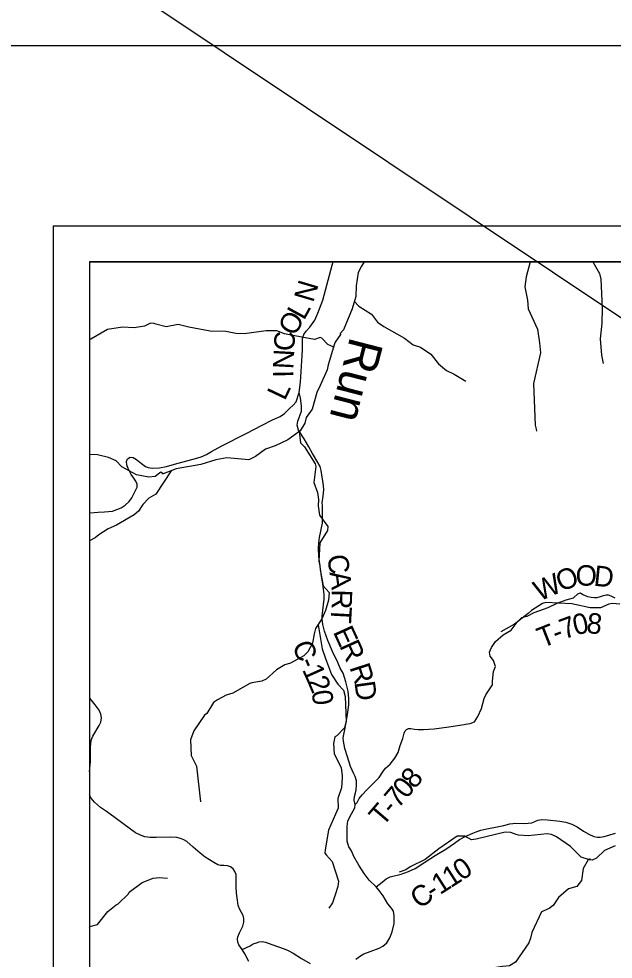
# Model space of a CAD drawing. Extents: x -1.8 to 75.7, y -2 to 25.
# Drawn here: x 1.905 to 3.552, y 18.965 to 21.574 of the extents above; entities that cross this region are included whole.
import ezdxf

# ---------------------------------------------------------------- set-up
doc = ezdxf.new("R2010")
doc.units = 0
for name, color, linetype in [('GM_X_County_Road', 7, 'Continuous'), ('GM_X_County_Road_Text', 7, 'Continuous'), ('GM_X_Minor_River', 7, 'Continuous'), ('GM_X_Minor_River_Text', 7, 'Continuous'), ('GM_X_Township', 7, 'Continuous'), ('GM_X_Township_Road', 7, 'Continuous'), ('GM_X_Township_Road_Text', 7, 'Continuous'), ('GM_X_Township_ROW', 7, 'Continuous'), ('SH_Border', 7, 'Continuous'), ('SH_Data', 7, 'Continuous'), ('TX_P_1', 7, 'Continuous')]:
    doc.layers.add(name, color=color, linetype=linetype)

msp = doc.modelspace()

# ---------------------------------------------------------------- linework, layer by layer
at = {"layer": 'GM_X_County_Road'}
for points in [[(2.6813, 20.5373), (2.685, 20.5663), (2.6879, 20.6104), (2.6901, 20.6398), (2.6908, 20.6552), (2.6903, 20.6757), (2.6911, 20.6875), (2.6944, 20.6986), (2.7004, 20.7075), (2.7107, 20.7182), (2.7245, 20.7376), (2.7332, 20.7569), (2.7469, 20.7938), (2.7732, 20.8906), (2.7756, 20.9)], [(2.4389, 20.3739), (2.4668, 20.3897), (2.5343, 20.4234), (2.5785, 20.447), (2.6077, 20.4615), (2.6288, 20.4708), (2.6406, 20.4791), (2.6548, 20.4931), (2.6644, 20.5022), (2.6733, 20.5116), (2.6813, 20.5373)], [(2.895, 19.1663), (2.8757, 19.184), (2.8613, 19.2025), (2.8465, 19.2258), (2.8334, 19.2502), (2.8262, 19.2657), (2.8195, 19.2767), (2.8147, 19.293), (2.8141, 19.3072), (2.8144, 19.3332), (2.8166, 19.3482), (2.8219, 19.3605), (2.8358, 19.3854), (2.8366, 19.394), (2.834, 19.4063), (2.8345, 19.4167), (2.8393, 19.4339), (2.8407, 19.4489), (2.8401, 19.4596), (2.8364, 19.4718), (2.8316, 19.4813), (2.8279, 19.4898), (2.8238, 19.4998), (2.8155, 19.5263), (2.808, 19.5498), (2.8041, 19.5704), (2.8034, 19.5793), (2.8088, 19.6069), (2.8155, 19.6438), (2.8192, 19.6704), (2.819, 19.6888), (2.8171, 19.7084), (2.8109, 19.7346), (2.8032, 19.759), (2.7954, 19.7727), (2.7884, 19.7882), (2.7742, 19.8187), (2.7609, 19.8492), (2.7517, 19.8755), (2.7472, 19.894), (2.745, 19.9098), (2.745, 19.9175), (2.7467, 19.9325), (2.7507, 19.9641), (2.7507, 19.9765), (2.7467, 20.0065), (2.7437, 20.0279), (2.7364, 20.082), (2.7351, 20.1058), (2.7359, 20.12), (2.7381, 20.135), (2.7464, 20.1744), (2.7459, 20.1931), (2.7461, 20.2148), (2.7458, 20.2241), (2.7456, 20.2314), (2.7483, 20.2499), (2.7496, 20.2676), (2.7488, 20.2788), (2.7424, 20.3206), (2.7394, 20.3321), (2.7333, 20.3434), (2.7185, 20.368), (2.7078, 20.3862), (2.695, 20.409), (2.6792, 20.4331), (2.676, 20.4462), (2.6778, 20.458), (2.6875, 20.4858), (2.688, 20.4992), (2.6848, 20.5228), (2.6813, 20.5373)], [(2.1, 20.2031), (2.1026, 20.2037), (2.1241, 20.2056), (2.1424, 20.206), (2.164, 20.2081), (2.1877, 20.2172), (2.1995, 20.2245), (2.2102, 20.2349), (2.2175, 20.2451), (2.229, 20.267), (2.2322, 20.2748), (2.2327, 20.2828), (2.2287, 20.2917), (2.2228, 20.2997), (2.2159, 20.3099), (2.2076, 20.3268), (2.2038, 20.3369), (2.2027, 20.3463), (2.2054, 20.3533), (2.2132, 20.3576), (2.2215, 20.3568), (2.2303, 20.3514), (2.2442, 20.3407), (2.2558, 20.3321), (2.2627, 20.3289), (2.2742, 20.327), (2.2946, 20.3284), (2.3141, 20.3321), (2.342, 20.3401), (2.3881, 20.3522), (2.4098, 20.3589), (2.4242, 20.3656), (2.4389, 20.3739)], [(2.1, 19.4845), (2.103, 19.5125), (2.1034, 19.5336), (2.1032, 19.5508), (2.1038, 19.5653), (2.1055, 19.5743), (2.1092, 19.5838), (2.1273, 19.6135), (2.1314, 19.6227), (2.1333, 19.6343), (2.1322, 19.6449), (2.1275, 19.6559), (2.1157, 19.6707), (2.1012, 19.689), (2.1, 19.6899)], [(2.5237, 18.9922), (2.5147, 19.0049), (2.5112, 19.0124), (2.5103, 19.0206), (2.5114, 19.0277), (2.5157, 19.0387), (2.5256, 19.0572), (2.5282, 19.0679), (2.528, 19.0785), (2.5258, 19.086), (2.5172, 19.1028), (2.5125, 19.114), (2.5101, 19.1288), (2.5078, 19.1484), (2.5065, 19.1656), (2.5071, 19.1891), (2.5065, 19.2003), (2.5032, 19.2089), (2.4983, 19.2156), (2.4914, 19.2211), (2.4832, 19.2244), (2.4727, 19.225), (2.4632, 19.2255), (2.4559, 19.2272), (2.4449, 19.2332), (2.4213, 19.2483), (2.4068, 19.2592), (2.3881, 19.2758), (2.3702, 19.2919), (2.3621, 19.2967), (2.3526, 19.3003), (2.3423, 19.3027), (2.3257, 19.304), (2.2848, 19.3025), (2.2689, 19.3027), (2.254, 19.3051), (2.242, 19.3092), (2.2282, 19.3158), (2.2144, 19.3255), (2.1718, 19.3574), (2.1473, 19.3746), (2.1307, 19.386), (2.1139, 19.4008), (2.1053, 19.412), (2.1, 19.4211)], [(3.1723, 19.3186), (3.1846, 19.323), (3.2013, 19.3272), (3.2253, 19.3319), (3.249, 19.3365), (3.2657, 19.3405), (3.2815, 19.3421), (3.3048, 19.3414), (3.3163, 19.3424), (3.326, 19.3437), (3.3432, 19.3505), (3.3543, 19.353), (3.3697, 19.3521), (3.4043, 19.3477), (3.4206, 19.3449), (3.4369, 19.3396), (3.4515, 19.3326), (3.4697, 19.3207), (3.4841, 19.3124), (3.4978, 19.3058), (3.508, 19.3035), (3.5155, 19.3035), (3.5264, 19.3056), (3.5585, 19.3149)], [(2.8388, 18.9649), (2.8516, 18.9746), (2.8607, 18.9799), (2.8782, 18.9869), (2.9033, 18.9957), (2.9135, 19.0014), (2.9247, 19.011), (2.9331, 19.0241), (2.9395, 19.0413), (2.9448, 19.0646), (2.9451, 19.0852), (2.9427, 19.0986), (2.9373, 19.1066), (2.9274, 19.1192), (2.914, 19.1406), (2.9033, 19.1559), (2.895, 19.1663), (2.9116, 19.1787), (2.9223, 19.1878), (2.9336, 19.1939), (2.9644, 19.2014), (2.9847, 19.2081), (3.0032, 19.2167), (3.0295, 19.2343), (3.0581, 19.253), (3.0878, 19.27), (3.1118, 19.2872), (3.126, 19.2977), (3.1415, 19.3058), (3.1629, 19.3151), (3.1723, 19.3186)], [(2.5237, 18.9922), (2.5452, 19.0027), (2.554, 19.0077), (2.5629, 19.0109), (2.571, 19.013), (2.579, 19.0139), (2.5883, 19.012), (2.6057, 19.0062), (2.6395, 18.9943), (2.6509, 18.9894), (2.6649, 18.9818), (2.6883, 18.9676), (2.712, 18.9536)], [(2.5422, 18.9588), (2.5306, 18.9797), (2.5237, 18.9922)]]:
    msp.add_lwpolyline(points, dxfattribs=at)
at = {"layer": 'GM_X_Minor_River'}
for points in [[(2.8614, 20.9), (2.8541, 20.8876), (2.8446, 20.8701), (2.839, 20.8329), (2.8387, 20.804)], [(3.322, 20.9), (3.3207, 20.8962), (3.3108, 20.8585), (3.307, 20.8302), (3.3142, 20.7935), (3.3161, 20.7691), (3.3416, 20.7129), (3.3476, 20.6747), (3.3505, 20.6473), (3.331, 20.5624), (3.3358, 20.4468), (3.3385, 20.4354), (3.339, 20.43)], [(3.495, 20.9), (3.5141, 20.8673), (3.5174, 20.852), (3.5214, 20.771), (3.5205, 20.7292), (3.5154, 20.6861), (3.5197, 20.6408), (3.5239, 20.6178)], [(2.8387, 20.804), (2.8285, 20.7697), (2.8047, 20.7115), (2.7949, 20.7005), (2.7964, 20.6986), (2.7813, 20.6765), (2.7798, 20.6719), (2.7621, 20.6137), (2.7587, 20.5997), (2.7399, 20.557), (2.7304, 20.5369), (2.7176, 20.4912), (2.7006, 20.4676), (2.6969, 20.4524), (2.684, 20.4311), (2.6663, 20.4181), (2.6496, 20.4059), (2.6145, 20.3895), (2.5877, 20.3803), (2.5601, 20.3597), (2.5563, 20.3578), (2.5416, 20.3502), (2.4807, 20.3557), (2.4509, 20.3507), (2.4085, 20.3373), (2.3409, 20.3254), (2.3042, 20.312), (2.3005, 20.312)], [(2.834, 20.791), (2.8472, 20.7768), (2.8817, 20.7541), (2.8981, 20.7327), (2.9158, 20.7203), (2.9731, 20.6881), (2.9971, 20.6691), (3.018, 20.6628), (3.0462, 20.6433), (3.068, 20.6167), (3.0902, 20.5986), (3.111, 20.588), (3.1433, 20.5688)], [(2.7772, 20.6633), (2.7605, 20.6702), (2.744, 20.6882), (2.7395, 20.6895), (2.7242, 20.6839), (2.6893, 20.6907), (2.6408, 20.7002), (2.6191, 20.7085), (2.5897, 20.7083), (2.5293, 20.7), (2.5055, 20.7011), (2.4785, 20.7065), (2.435, 20.7071), (2.376, 20.7189), (2.3464, 20.7255), (2.3125, 20.719), (2.2844, 20.7271), (2.2799, 20.7284), (2.2698, 20.7295), (2.2529, 20.7217), (2.2244, 20.7169), (2.1919, 20.7187), (2.1505, 20.7117), (2.1044, 20.6854), (2.1, 20.6848)], [(2.6811, 20.4289), (2.6811, 20.429), (2.6849, 20.3977), (2.6963, 20.3863), (2.7255, 20.339), (2.7272, 20.3322), (2.7217, 20.2875), (2.7322, 20.2602), (2.7346, 20.24), (2.7337, 20.2226), (2.7374, 20.1966), (2.7611, 20.1659), (2.7596, 20.1542), (2.7385, 20.1203), (2.7362, 20.0698), (2.7385, 20.0569), (2.7397, 20.0454), (2.7478, 20.0011), (2.7642, 19.9824), (2.7624, 19.9615), (2.7544, 19.9329), (2.7442, 19.9093), (2.7271, 19.8822), (2.7233, 19.8675), (2.718, 19.8418), (2.7059, 19.8183), (2.6942, 19.8065), (2.657, 19.7868), (2.6413, 19.782), (2.6182, 19.7683), (2.5902, 19.7418), (2.578, 19.7362), (2.5499, 19.7321), (2.5445, 19.7296), (2.498, 19.703), (2.4793, 19.6979), (2.4547, 19.6843), (2.4442, 19.677), (2.4256, 19.6465), (2.419, 19.6417), (2.3893, 19.599), (2.3799, 19.5739), (2.3824, 19.5305), (2.3966, 19.5008), (2.4082, 19.402)], [(2.3042, 20.312), (2.2984, 20.3158), (2.2826, 20.3042), (2.2648, 20.3025), (2.2309, 20.3092), (2.1904, 20.3307), (2.1739, 20.3475), (2.153, 20.3573), (2.123, 20.364), (2.1, 20.3651)], [(2.327, 20.3203), (2.2841, 20.2551), (2.2649, 20.2444), (2.2481, 20.2263), (2.2366, 20.2077), (2.2245, 20.1978), (2.1753, 20.169), (2.1523, 20.1591), (2.1265, 20.1425), (2.116, 20.1344), (2.1, 20.1262)], [(3.5698, 19.9499), (3.5495, 19.9521), (3.5396, 19.9497), (3.517, 19.9398), (3.4882, 19.9396), (3.4375, 19.9507), (3.3651, 19.9545), (3.3556, 19.9522), (3.3255, 19.9326), (3.3158, 19.9238), (3.2786, 19.8942), (3.2405, 19.873)], [(2.7338, 19.8928), (2.7455, 19.8265), (2.7541, 19.7989), (2.7713, 19.7554), (2.7886, 19.7283), (2.8044, 19.7115), (2.8091, 19.6935), (2.8119, 19.6243), (2.8069, 19.6066), (2.7854, 19.5852), (2.78, 19.5816), (2.7768, 19.5639), (2.7782, 19.535), (2.7975, 19.4971), (2.8006, 19.4739), (2.8008, 19.4685), (2.7984, 19.4405), (2.7888, 19.4108), (2.7895, 19.3838), (2.7826, 19.3673), (2.7627, 19.3228), (2.7535, 19.2684), (2.7529, 19.2589), (2.7565, 19.2543), (2.7726, 19.2359), (2.7902, 19.1814), (2.789, 19.1666), (2.7824, 19.1467), (2.7737, 19.1215), (2.7634, 19.1071)], [(3.5571, 19.2793), (3.528, 19.2669), (3.5054, 19.2452), (3.4931, 19.2403), (3.4864, 19.2409), (3.4631, 19.2481), (3.4334, 19.2775), (3.3946, 19.3046), (3.3808, 19.3115), (3.3691, 19.3134), (3.3164, 19.3071), (3.2889, 19.3095), (3.2832, 19.3108), (3.2679, 19.3166), (3.2528, 19.3174), (3.1721, 19.2984), (3.1588, 19.2961), (3.141, 19.3069), (3.1194, 19.3061), (3.0689, 19.2713), (3.0306, 19.2421), (2.9891, 19.2218), (2.9768, 19.2127), (2.9584, 19.2068)], [(3.4876, 19.2435), (3.4826, 19.241), (3.4682, 19.2168), (3.4642, 19.1831), (3.4509, 19.1668), (3.428, 19.1607), (3.4004, 19.1365), (3.3858, 19.1138), (3.3742, 19.1062), (3.3531, 19.0963), (3.3264, 19.0394), (3.3226, 19.0236), (3.318, 19.0108), (3.2812, 18.9573), (3.2647, 18.9472), (3.2446, 18.9448), (3.2396, 18.9442), (3.2131, 18.9404), (3.1875, 18.9314), (3.1704, 18.9175), (3.1389, 18.8995), (3.1138, 18.8821), (3.0941, 18.8561)], [(2.1, 19.0545), (2.1015, 19.0556), (2.1221, 19.0614), (2.1515, 19.0977), (2.1744, 19.1156), (2.1798, 19.1188), (2.2089, 19.1464), (2.2106, 19.1509), (2.2466, 19.1782), (2.2764, 19.1898), (2.2935, 19.1923), (2.3165, 19.1901)]]:
    msp.add_lwpolyline(points, dxfattribs=at)
at = {"layer": 'GM_X_Township'}
msp.add_lwpolyline([(6.4874, 20.9), (2.1, 20.9), (2.1, 17.3659)], dxfattribs=at)
at = {"layer": 'GM_X_Township_Road'}
for points in [[(3.3137, 19.9172), (3.3326, 19.9269), (3.3712, 19.9411), (3.3967, 19.9526), (3.4214, 19.9619), (3.4414, 19.9678), (3.4538, 19.9789), (3.461, 19.9819), (3.4676, 19.9771), (3.481, 19.9717), (3.4905, 19.9696), (3.5003, 19.9688), (3.5075, 19.9688), (3.5165, 19.9711), (3.525, 19.9745), (3.5319, 19.9758), (3.5378, 19.9758), (3.545, 19.9732), (3.5561, 19.9681)], [(2.8366, 19.394), (2.842, 19.4001), (2.8476, 19.4111), (2.8559, 19.421), (2.8701, 19.4358), (2.8915, 19.4569), (2.9031, 19.469), (2.9132, 19.4848), (2.9207, 19.4949), (2.9336, 19.5065), (2.947, 19.5225), (2.9561, 19.5386), (2.9616, 19.5579), (2.9683, 19.577), (2.9724, 19.5924), (2.9755, 19.5988), (2.9788, 19.6022), (2.9845, 19.605), (2.9912, 19.605), (3.0015, 19.6034), (3.0112, 19.6022), (3.0261, 19.6024), (3.0552, 19.6045), (3.0961, 19.6101), (3.1388, 19.6163), (3.1422, 19.6169)]]:
    msp.add_lwpolyline(points, dxfattribs=at)
at = {"layer": 'GM_X_Township_ROW'}
msp.add_lwpolyline([(3.1422, 19.6169), (3.1557, 19.6194), (3.1678, 19.6238), (3.1766, 19.6389), (3.1866, 19.661), (3.1946, 19.6885), (3.1984, 19.6988), (3.2169, 19.7263), (3.2172, 19.7364), (3.22, 19.7629), (3.2252, 19.7775), (3.2203, 19.7935), (3.211, 19.8061), (3.2092, 19.8166), (3.2141, 19.8302), (3.2252, 19.8464), (3.2465, 19.8652), (3.2689, 19.8783), (3.2858, 19.9004), (3.299, 19.9128), (3.3121, 19.9164), (3.3137, 19.9172)], dxfattribs=at)
at = {"layer": 'SH_Border'}
msp.add_lwpolyline([(1.5, 21.5), (33.5, 21.5), (33.5, 0.5), (1.5, 0.5)], close=True, dxfattribs=at)
at = {"layer": 'SH_Data'}
for p, q in [((2, 21), (9, 21)), ((2, 21), (2, 14)), ((2.1, 20.9), (2.1, 14.1)), ((2.1, 20.9), (8.9, 20.9))]:
    msp.add_line(p, q, dxfattribs=at)
at = {"layer": 'TX_P_1'}
msp.add_line((-1.8436, 24.3711), (37.5745, -2.0199), dxfattribs=at)

# ---------------------------------------------------------------- texts
at = {"layer": 'GM_X_County_Road_Text'}
for s, rotation, p in [('N', 73.4185, (2.7204, 20.7848)), ('L', 61.2064, (2.6948, 20.7354)), ('O', 59.2714, (2.6683, 20.6906)), ('C', 86.9318, (2.6678, 20.6509)), ('N', 86.9277, (2.6652, 20.601)), ('I', 91.2033, (2.6657, 20.5788)), ('L', 64.6837, (2.6416, 20.5125)), ('C', 277.6924, (2.7591, 20.0846)), ('A', 277.4707, (2.7653, 20.0384)), ('R', 269.4223, (2.7717, 19.9909)), ('T', 266.8141, (2.7712, 19.9449)), ('E', 294.5102, (2.7744, 19.8733)), ('R', 294.1713, (2.792, 19.8347)), ('C', 290.8671, (2.6614, 19.8368)), ('1', 294.1433, (2.689, 19.7686)), ('-', 294.1, (2.6794, 19.7899)), ('R', 288.1418, (2.8204, 19.7751)), ('2', 293.0964, (2.7032, 19.7369)), ('D', 277.9042, (2.8344, 19.7333)), ('0', 277.2845, (2.7158, 19.7087)), ('0', 34.2863, (3.1322, 19.1814)), ('1', 32.6227, (3.0716, 19.1427)), ('1', 32.4848, (3.1011, 19.1616)), ('C', 35.809, (3.0151, 19.1028)), ('-', 34.1415, (3.0526, 19.1298))]:
    msp.add_text(s, height=0.0568, rotation=rotation, dxfattribs=at).set_placement(p)
at = {"layer": 'GM_X_Minor_River_Text'}
msp.add_text('Run', height=0.0947, rotation=255.514, dxfattribs=at).set_placement((2.8234, 20.6947))
at = {"layer": 'GM_X_Township_Road_Text'}
for s, rotation, p in [('W', 23.5472, (3.3471, 19.9572)), ('O', 22.7387, (3.4073, 19.9834)), ('O', 359.7887, (3.4475, 20.0015)), ('D', 354.3043, (3.4961, 20.0014)), ('7', 20.4044, (3.4157, 19.8516)), ('0', 12.6919, (3.4466, 19.8633)), ('8', 353.3894, (3.4757, 19.8707)), ('T', 21.4409, (3.3547, 19.8277)), ('-', 21.255, (3.3942, 19.8432)), ('8', 50.2182, (3.0014, 19.435)), ('0', 49.7228, (2.9785, 19.4078)), ('7', 49.5559, (2.9557, 19.3811)), ('T', 49.4986, (2.9129, 19.331)), ('-', 49.5025, (2.9405, 19.3633))]:
    msp.add_text(s, height=0.0568, rotation=rotation, dxfattribs=at).set_placement(p)

doc.saveas('drawing.dxf')
